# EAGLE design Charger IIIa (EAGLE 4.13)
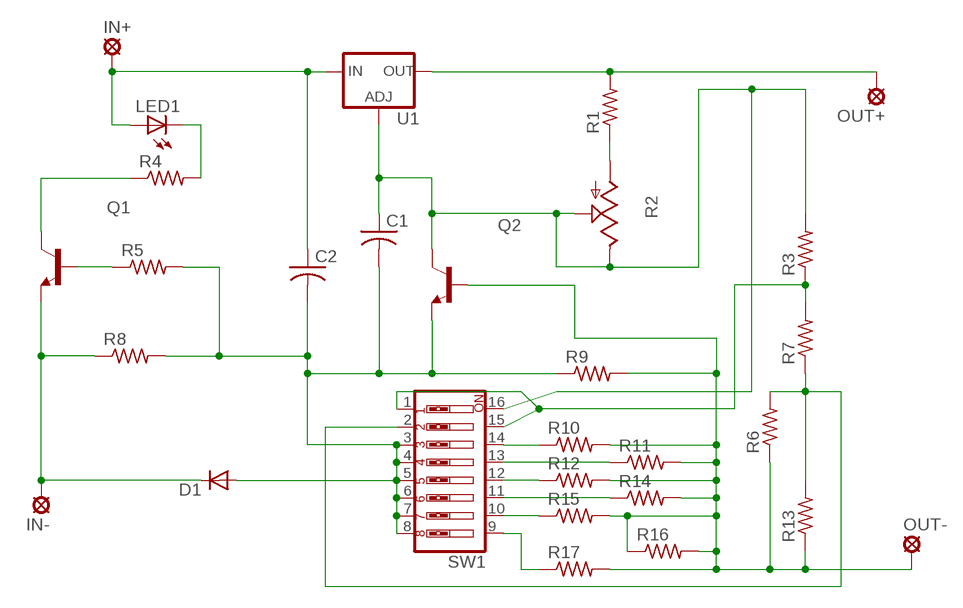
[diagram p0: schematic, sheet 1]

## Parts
C1  C-US050-024X044  [C050-024X044]
C2  C-US050-024X044  [C050-024X044]
D1  DIODE-C1702-05  [C1702-05]
IN+  SE14  [SE14]
IN-  SE14  [SE14]
LED1  LED5MM  [LED5MM]
OUT+  SE14  [SE14]
OUT-  SE14  [SE14]
Q1  2N3904  [TO92]
Q2  2N3904  [TO92]
R1  R-US_0207/2V  [0207/2V]
R2  TRIM_US-PTSPIN  [PT-SPIN]
R3  R-US_0207/2V  [0207/2V]
R4  R-US_0207/2V  [0207/2V]
R5  R-US_0207/2V  [0207/2V]
R6  R-US_0207/2V  [0207/2V]
R7  R-US_0207/2V  [0207/2V]
R8  R-US_0207/2V  [0207/2V]
R9  R-US_0207/2V  [0207/2V]
R10  R-US_0207/2V  [0207/2V]
R11  R-US_0207/2V  [0207/2V]
R12  R-US_0207/2V  [0207/2V]
R13  R-US_0207/2V  [0207/2V]
R14  R-US_0207/2V  [0207/2V]
R15  R-US_0207/2V  [0207/2V]
R16  R-US_0207/2V  [0207/2V]
R17  R-US_0207/2V  [0207/2V]
SW1  SW_DIP-8  [EDG-08]
U1  LM317TS  [317TS]

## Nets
N$1: C1.2 C2.2 D1.A Q2.3(E) R5.2 R8.2 R9.1 SW1.3 SW1.4 SW1.5 SW1.6 SW1.7 SW1.8
N$2: OUT-.MP Q2.2(B) R6.1 R9.2 R10.2 R11.2 R12.2 R13.1 R14.2 R15.2 R16.1 R16.2 R17.2
N$3: R17.1 SW1.9
N$4: R15.1 SW1.10
N$5: R14.1 SW1.11
N$6: R12.1 SW1.12
N$7: R11.1 SW1.13
N$8: R10.1 SW1.14
N$10: C1.1 Q2.1(C) R2.E R2.S R3.2 SW1.16 U1.1(ADJ)
N$11: R1.1 R2.A
N$12: Q1.2(B) R5.1
N$13: LED1.K(C) R4.2
N$14: Q1.1(C) R4.1
N$15: OUT+.MP R1.2 U1.2(OUT)
N$16: R3.1 R7.2 SW1.1 SW1.15
N$17: C2.1 IN+.MP LED1.A U1.3(IN)
N$18: D1.C IN-.MP Q1.3(E) R8.1
N$20: R6.2 R7.1 R13.2 SW1.2

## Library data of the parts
C1 C2 = rcl:C-US: CAPACITOR, American symbol
D1 = diode:DIODE-: DIODE
IN+ IN- OUT+ OUT- = solpad:SE14: SOLDER PAD
LED1 = led:LED: LED
Q1 Q2 = 00 Dales Common:2N3904: NPN Transistor
R1 R3-R17 = rcl:R-US_: RESISTOR, American symbol
R2 = pot:TRIM_US-: POTENTIOMETER
SW1 = special:SW_DIP-8: DIP SWITCH
U1 = 00 Dales Common:LM317TS: VOLTAGE REGULATOR

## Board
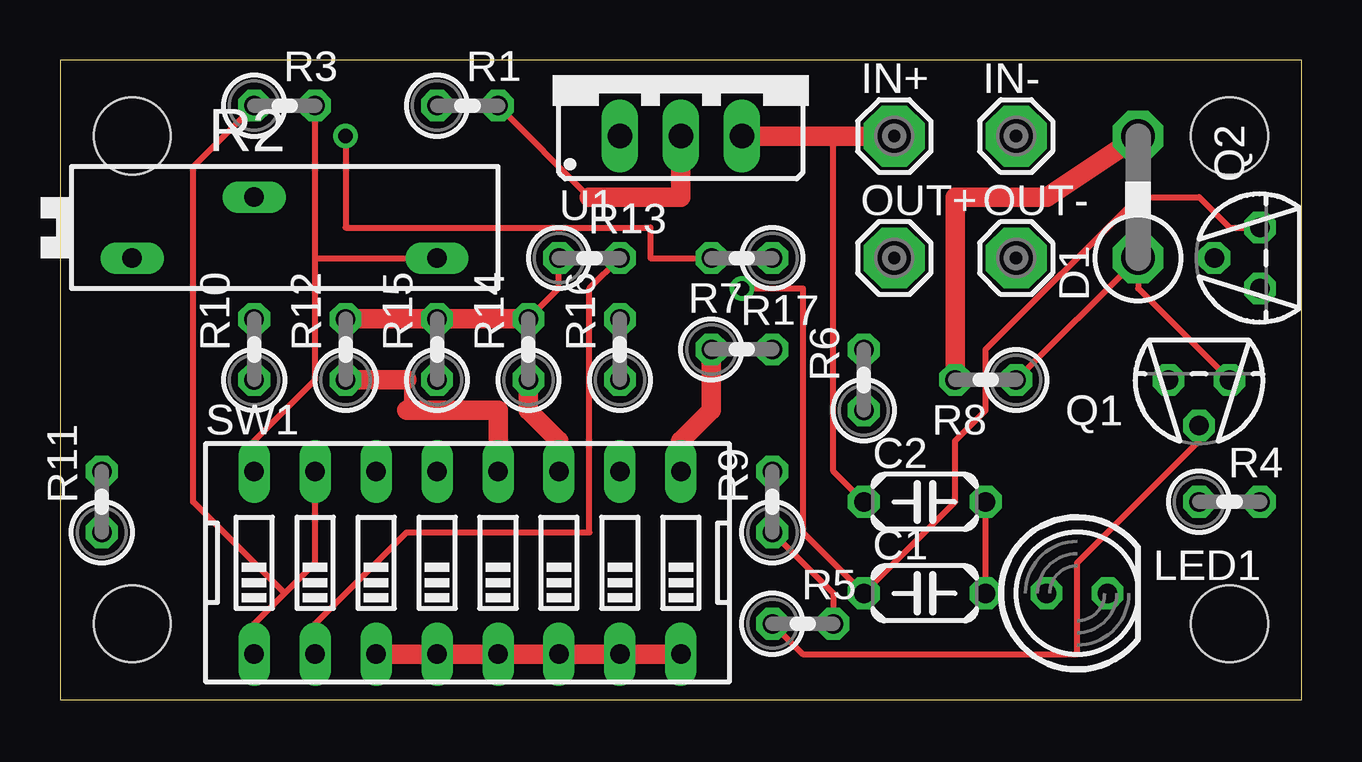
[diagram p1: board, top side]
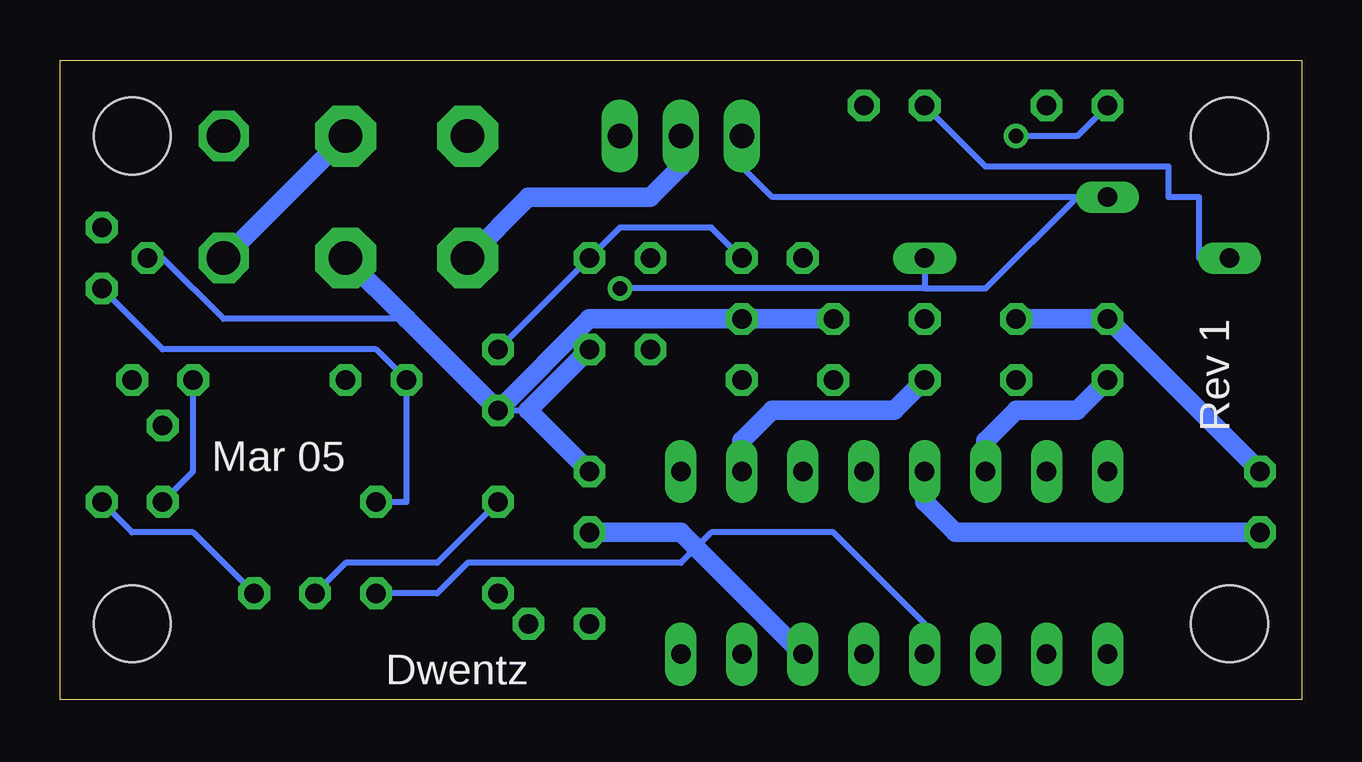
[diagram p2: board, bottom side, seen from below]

Size 51.74 x 26.66 mm. Coordinates in mm from the lower left corner, seen from the top.
Outline: 0,0 51.74,0 51.74,26.66 0,26.66 0,0
Copper layers (1*16): Top 0.035mm / dielectric 1.5mm / Bottom 0.035mm
Design rules "default": minimum track width 10mil, minimum drill 24mil, track to track 8mil, track to pad 8mil, pad to pad 8mil, via to via 8mil, smd to smd 8mil, copper to edge 40mil, drill to drill 8mil, minimum pad ring 10mil, minimum via ring 8mil, stop-mask expansion 4mil, vias tented up to drill 0mil, thermal gap 10mil
Holes 3.2 mm at 3.01,23.49 48.73,23.49 3.01,3.17 48.73,3.17

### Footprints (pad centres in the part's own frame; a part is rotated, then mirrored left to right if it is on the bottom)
C050-024X044 = drill 0.813 octagon: 1 -2.54,0; 2 2.54,0
C1702-05 = drill 1.397 octagon: A 2.54,0; C -2.54,0
SE14 = drill 1.397 pad 2.54 octagon: MP 0,0
LED5MM = drill 0.813 octagon: A -1.27,0; K 1.27,0
TO92 = drill 0.813 octagon: 1 1.27,0; 2 0,1.905; 3 -1.27,0
0207/2V = drill 0.813 octagon: 1 -1.27,0; 2 1.27,0
PT-SPIN = drill 0.813 long: A -6.35,-1.27; E 6.35,-1.27; S -1.27,1.27
EDG-08 = drill 0.813 long: 1 -8.89,-3.81; 2 -6.35,-3.81; 3 -3.81,-3.81; 4 -1.27,-3.81; 5 1.27,-3.81; 6 3.81,-3.81; 7 6.35,-3.81; 8 8.89,-3.81; 9 8.89,3.81; 10 6.35,3.81; 11 3.81,3.81; 12 1.27,3.81; 13 -1.27,3.81; 14 -3.81,3.81; 15 -6.35,3.81; 16 -8.89,3.81
317TS = drill 1.016 long: 1 -2.54,-2.54; 2 0,-2.54; 3 2.54,-2.54

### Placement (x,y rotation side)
C1  36.03,4.44 0 top
C2  36.03,8.25 0 top
D1  44.92,20.95 90 top
IN+  34.76,23.49 0 top
IN-  39.84,23.49 0 top
LED1  42.38,4.44 0 top
OUT+  34.76,18.41 0 top
OUT-  39.84,18.41 0 top
Q1  47.46,13.33 180 top
Q2  50,18.41 90 top
R1  16.98,24.76 0 top
R2  9.36,19.68 0 top
R3  9.36,24.76 0 top
R4  48.73,8.25 0 top
R5  30.95,3.17 0 top
R6  33.49,13.33 90 top
R7  28.41,18.41 180 top
R8  38.57,13.33 180 top
R9  29.68,8.25 90 top
R10  8.09,14.6 90 top
R11  1.74,8.25 90 top
R12  11.9,14.6 90 top
R13  22.06,18.41 0 top
R14  19.52,14.6 90 top
R15  15.71,14.6 90 top
R16  23.33,14.6 90 top
R17  28.41,14.6 0 top
SW1  16.98,5.71 0 top
U1  25.87,26.03 0 top

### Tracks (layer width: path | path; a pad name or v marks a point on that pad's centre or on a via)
N$1
  Top 0.254: C1.2 C2.2 | R9.1 32.22,4.44 R5.2
  Top 0.813: SW1.8 SW1.7 SW1.6 SW1.5 SW1.4 SW1.3 | D1.A 41.11,20.95 37.3,20.95 R8.2
  Bottom 0.254: C2.2 37.3,8.25 R8.2 38.57,14.6 47.46,14.6 Q2.3 | C1.2 36.03,4.44 34.76,5.71 25.87,5.71 24.6,6.98 19.52,6.98 15.71,3.17 SW1.4
  Bottom 0.813: SW1.6 25.87,6.98 R9.1
N$2
  Top 0.254: R16.2 R16.1 | R14.2 20.79,17.14 R13.1
  Top 0.813: R12.2 R15.2 R14.2
  Bottom 0.254: R6.1 32.22,12.06 | 37.3,15.87 44.92,15.87 47.46,18.41 Q2.2
  Bottom 0.813: OUT-.MP 37.3,15.87 R6.1 29.68,15.87 R16.2 R14.2 | R9.2 32.22,12.06 R17.2 | R11.2 R10.2 R12.2
N$3
  Top 0.813: R17.1 27.14,12.06 25.87,10.79 SW1.9
N$4
  Bottom 0.813: R15.1 16.98,12.06 22.06,12.06 23.33,10.79 SW1.10
N$5
  Top 0.813: R14.1 19.52,12.06 20.79,10.79 SW1.11
N$6
  Top 0.254: 14.44,13.33 14.44,12.06
  Top 0.813: R12.1 14.44,13.33 | 14.44,12.06 18.25,12.06 SW1.12
N$7
  Bottom 0.813: R11.1 14.44,6.98 15.71,8.25 SW1.13
N$8
  Bottom 0.813: R10.1 9.36,12.06 11.9,12.06 13.17,10.79 SW1.14
N$10  (via drill 0.61)
  Top 0.254: 10.63,18.41 R3.2 | 10.63,18.41 10.63,13.33 8.09,10.79 SW1.16 | 10.63,18.41 R2.E | Q2.1 48.73,19.68 47.46,20.95 44.92,20.95 38.57,14.6 38.57,12.06 37.3,10.79 37.3,8.25 C1.1 30.95,6.98 30.95,17.14 v28.41,17.14
  Bottom 0.254: 9.36,20.95 22.06,20.95 23.33,22.22 U1.1 | 9.36,20.95 13.17,17.14 15.71,17.14 | 15.71,17.14 v28.41,17.14 | 9.36,20.95 R2.S | R2.E 15.71,17.14
N$11
  Bottom 0.254: R1.1 13.17,22.22 5.55,22.22 5.55,20.95 4.28,20.95 4.28,18.41 R2.A
N$12
  Top 0.254: R5.1 30.95,1.9 42.38,1.9 42.38,5.71 47.46,10.79 Q1.2
N$13
  Bottom 0.254: LED1.K 46.19,6.98 48.73,6.98 R4.2
N$14
  Bottom 0.254: R4.1 46.19,9.52 Q1.1
N$15
  Top 0.254: R1.2 22.06,20.95
  Top 0.813: 22.06,20.95 25.87,20.95 U1.2
  Bottom 0.254: U1.2 25.87,22.22
  Bottom 0.813: OUT+.MP 32.22,20.95 27.14,20.95 25.87,22.22
N$16  (via drill 0.61)
  Top 0.254: 9.36,4.44 10.63,5.71 SW1.15 | 9.36,4.44 8.09,3.17 SW1.1 | R3.1 5.55,22.22 5.55,8.25 9.36,4.44 | R7.2 24.6,18.41 24.6,19.68 11.9,19.68 v11.9,23.49
  Bottom 0.254: v11.9,23.49 9.36,23.49 R3.1
N$17
  Top 0.254: C2.1 32.22,9.52 32.22,23.49
  Top 0.813: IN+.MP 32.22,23.49 U1.3
  Bottom 0.254: C2.1 36.03,5.71 39.84,5.71 LED1.A
N$18
  Top 0.254: R8.1 D1.C 44.92,17.14 Q1.3
  Bottom 0.813: D1.C IN-.MP
N$20
  Top 0.254: R13.2 22.06,17.14 22.06,6.98 14.44,6.98 10.63,3.17 SW1.2
  Bottom 0.254: R6.2 R7.1 28.41,19.68 24.6,19.68 R13.2

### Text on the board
bPlace: Rev 1 | Mar 05 | Dwentz
tNames: R3 | R1 | IN+ | IN- | R2 | Q2 | OUT+ | OUT- | U1 | R13 | R7 | D1 | R17 | R10 | R12 | R15 | R14 | R16 | R6 | R8 | Q1 | SW1 | C2 | R4 | R11 | R9 | C1 | R5 | LED1
tValues: SE14 | SE14 | SE14 | SE14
